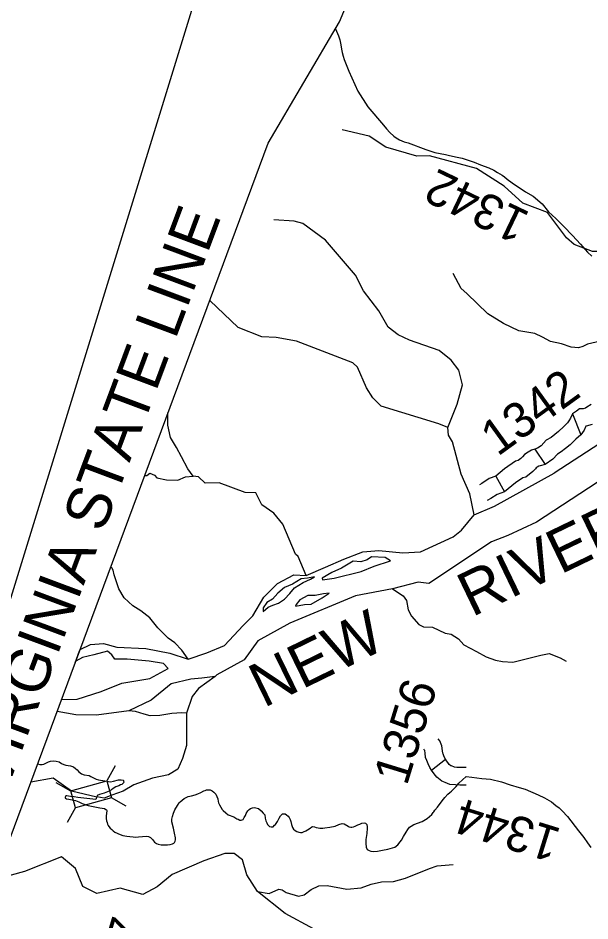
# Model space of a CAD drawing. Extents: x 1347947 to 1350662, y 1027710 to 1030532.
# Drawn here: x 1348130.6 to 1348203.5, y 1028931.2 to 1029046.3 of the extents above; entities that cross this region are included whole.
import ezdxf

# ---------------------------------------------------------------- set-up
doc = ezdxf.new("R2010")
doc.units = 0
for name, color, linetype in [('Default', 7, 'Continuous'), ('Prop Leader Line Light', 7, 'Continuous'), ('Prop WCC CELL', 7, 'Continuous'), ('Sheet Data Field CELL', 7, 'Continuous')]:
    doc.layers.add(name, color=color, linetype=linetype)

msp = doc.modelspace()

# ---------------------------------------------------------------- linework, layer by layer
at = {"layer": 'Default'}
for p, q in [((1348201.31, 1028995.87), (1348202.37, 1028993.22)), ((1348196.49, 1028991.39), (1348197.83, 1028989.42)), ((1348191.55, 1028987.92), (1348192.66, 1028985.91)), ((1348137.86, 1028964.14), (1348138.42, 1028965.64)), ((1348183.33, 1028950.42), (1348185.12, 1028951.83)), ((1348142.97, 1028950.98), (1348141.9, 1028949.08)), ((1348137.31, 1028947.76), (1348135.42, 1028948.83)), ((1348144.39, 1028945.86), (1348142.5, 1028946.93)), ((1348137.9, 1028945.66), (1348136.83, 1028943.76))]:
    msp.add_line(p, q, dxfattribs=at)
for points in [[(1348083.52, 1028822.71), (1348089.97, 1028837.63), (1348104.26, 1028873.21), (1348113.82, 1028899.5), (1348162.49, 1029030.38), (1348171.57, 1029045.86), (1348180.52, 1029067.26), (1348186.85, 1029082.58), (1348194.68, 1029101.03), (1348199.8, 1029113.4)], [(1348171.06, 1029044.99), (1348171.45, 1029044.09), (1348171.62, 1029043.57), (1348171.75, 1029042.94), (1348171.85, 1029042.39), (1348171.94, 1029041.96), (1348172.04, 1029041.47), (1348172.17, 1029041.05), (1348172.43, 1029040.42), (1348172.78, 1029039.59), (1348173.93, 1029037.02), (1348175.2, 1029035.01), (1348177.2, 1029032.7), (1348177.58, 1029032.24), (1348178.01, 1029031.77), (1348178.52, 1029031.29), (1348178.81, 1029031.08), (1348179.01, 1029030.95), (1348179.23, 1029030.83), (1348179.85, 1029030.58), (1348180.36, 1029030.43), (1348182.6, 1029029.58), (1348183.77, 1029029.2), (1348185.13, 1029028.94), (1348185.62, 1029028.8), (1348186.58, 1029028.61), (1348187.23, 1029028.49), (1348187.87, 1029028.27), (1348188.77, 1029027.97), (1348189.58, 1029027.62), (1348190.64, 1029027.23), (1348191.28, 1029026.95), (1348191.73, 1029026.67), (1348192.05, 1029026.48), (1348192.35, 1029026.33), (1348192.63, 1029026.09), (1348192.99, 1029025.8), (1348193.6, 1029025.32), (1348195.34, 1029024.17), (1348196.31, 1029023.63), (1348197.45, 1029022.65), (1348198.26, 1029021.62), (1348199.21, 1029020.77), (1348200.21, 1029019.77), (1348201.3, 1029018.63), (1348202.33, 1029017.5), (1348203.21, 1029016.5), (1348203.79, 1029015.99)], [(1348204.8, 1029016.57), (1348203.86, 1029016.56), (1348201.53, 1029017.46), (1348200.55, 1029018.32), (1348198.13, 1029021.54), (1348194.97, 1029022.73), (1348192.59, 1029024.93), (1348189.06, 1029027.18), (1348183.06, 1029028.77), (1348181.45, 1029028.74), (1348177.5, 1029029.87), (1348175.38, 1029031.29), (1348171.91, 1029032.08)], [(1348185.39, 1028994.14), (1348186.59, 1028997.12), (1348187.29, 1028999.59), (1348186.83, 1029001.45), (1348185.84, 1029002.73), (1348184.32, 1029003.94), (1348180.54, 1029005.27), (1348179.07, 1029005.95), (1348177.8, 1029006.91), (1348176.6, 1029009.03), (1348174.67, 1029011.57), (1348173.65, 1029013.54), (1348169.8, 1029018.04), (1348166.9, 1029020.16), (1348165.8, 1029020.46), (1348163.2, 1029020.6)], [(1348207.84, 1029006.59), (1348205.83, 1029005.34), (1348203.22, 1029004.76), (1348202.64, 1029004.45), (1348202.08, 1029004.3), (1348201.14, 1029004.36), (1348199.91, 1029004.8), (1348198.52, 1029005.08), (1348197.49, 1029005.64), (1348196.53, 1029006.1), (1348194.47, 1029006.44), (1348192.53, 1029007.38), (1348190.52, 1029008.63), (1348187.82, 1029011.23), (1348187.13, 1029011.86), (1348186.11, 1029013.79)], [(1348185.39, 1028994.14), (1348184.28, 1028994.61), (1348176.91, 1028996.85), (1348175.84, 1028997.91), (1348175.02, 1028999.21), (1348173.89, 1029001.82), (1348173.31, 1029002.36), (1348166.12, 1029005.14), (1348163.51, 1029005.62), (1348161.66, 1029005.68), (1348158.67, 1029006.89), (1348155.04, 1029010.35)], [(1348203.69, 1028997.05), (1348203.15, 1028996.72), (1348202.96, 1028996.62), (1348202.69, 1028996.53), (1348202.22, 1028996.53), (1348201.83, 1028996.23), (1348201.31, 1028995.87), (1348201.04, 1028995.33), (1348200.86, 1028994.97), (1348200.68, 1028994.72), (1348200.2, 1028994.26), (1348199.55, 1028993.63), (1348199.05, 1028993.24), (1348198.59, 1028992.88), (1348197.97, 1028992.51), (1348197.31, 1028991.8), (1348196.86, 1028991.49), (1348196.49, 1028991.39), (1348196.1, 1028991.23), (1348195.64, 1028990.99), (1348195.21, 1028990.68), (1348194.94, 1028990.4), (1348194.74, 1028990.18), (1348194.4, 1028989.91), (1348194.04, 1028989.84), (1348192.66, 1028988.85), (1348191.55, 1028987.92), (1348190.7, 1028987.65), (1348189.76, 1028987), (1348189.43, 1028986.84)], [(1348152.9, 1028987.91), (1348152.22, 1028988.86), (1348151.43, 1028990.4), (1348150.78, 1028991.57), (1348150.01, 1028992.86), (1348149.68, 1028994.44), (1348149.68, 1028996.01)], [(1348203.82, 1028994.53), (1348203.06, 1028994.29), (1348203.03, 1028994.29), (1348202.79, 1028993.79), (1348202.37, 1028993.22), (1348201.76, 1028992.64), (1348201.03, 1028991.92), (1348200.43, 1028991.47), (1348199.88, 1028991.03), (1348199.39, 1028990.74), (1348198.79, 1028990.09), (1348197.83, 1028989.42), (1348197.2, 1028989.25), (1348197.04, 1028989.19), (1348196.82, 1028989.07), (1348196.69, 1028988.98), (1348196.58, 1028988.86), (1348196.27, 1028988.52), (1348195.38, 1028987.82), (1348194.96, 1028987.73), (1348194.04, 1028987.07), (1348192.66, 1028985.91), (1348191.69, 1028985.6), (1348190.91, 1028985.07), (1348190.45, 1028984.83)], [(1348221.39, 1028995.36), (1348214.11, 1028992.74), (1348211.12, 1028992.92), (1348209.06, 1028993.68), (1348207.27, 1028993.48), (1348204.79, 1028992.09), (1348198.97, 1028988.31)], [(1348188.79, 1028983), (1348188.2, 1028985.68), (1348187.13, 1028988.17), (1348186.02, 1028992.3), (1348185.49, 1028993.17), (1348185.39, 1028994.14)], [(1348224.13, 1028992.17), (1348222.1, 1028990.98), (1348211.59, 1028988.12), (1348206.93, 1028987.7), (1348204.48, 1028987.13), (1348196.74, 1028982.06), (1348193.07, 1028980.37), (1348191, 1028979.57), (1348182.98, 1028974.25), (1348181.62, 1028974.41), (1348178.33, 1028973.56), (1348173.63, 1028972.68), (1348165.25, 1028969.18), (1348161.18, 1028966.93), (1348159.42, 1028964.51), (1348155.92, 1028962.61), (1348155.72, 1028962.4)], [(1348138.49, 1028965.83), (1348139.8, 1028966.46), (1348141.47, 1028966.6), (1348143.19, 1028966.12), (1348146.89, 1028965.94), (1348149.95, 1028965.37), (1348152.29, 1028964.61), (1348154.65, 1028965.38), (1348156.93, 1028966.34), (1348159.3, 1028968.9), (1348160.55, 1028970.11), (1348161.92, 1028972.49), (1348163.68, 1028974.22), (1348165.75, 1028975.33), (1348167.33, 1028975.24), (1348169.82, 1028976.31), (1348172.13, 1028977.35), (1348174.56, 1028978.27), (1348176.59, 1028978.46), (1348179.65, 1028978.15), (1348181.91, 1028978.27), (1348186.09, 1028980.21), (1348187.14, 1028981.06), (1348188.79, 1028983), (1348191.38, 1028984.12), (1348198.97, 1028988.31)], [(1348146.7, 1028988.01), (1348146.99, 1028988.02), (1348147.39, 1028988.31), (1348147.97, 1028988.04), (1348148.27, 1028987.73), (1348149.51, 1028987.47), (1348150.95, 1028987.41), (1348151.96, 1028987.83), (1348152.9, 1028987.91)], [(1348167.33, 1028975.24), (1348166.3, 1028977.7), (1348165.97, 1028977.99), (1348164.35, 1028981.79), (1348163.2, 1028983.21), (1348161.66, 1028984.27), (1348160.92, 1028985.81), (1348159.54, 1028985.86), (1348156.22, 1028987.09), (1348154.47, 1028987.04), (1348153.58, 1028987.86), (1348152.9, 1028987.91)], [(1348169.4, 1028974.71), (1348170.9, 1028974.9), (1348174.34, 1028975.79), (1348176.03, 1028976.46), (1348178.09, 1028977.15), (1348177.4, 1028977.57), (1348175.67, 1028977.65), (1348175.11, 1028977.24), (1348174.32, 1028976.99), (1348173.33, 1028977.08), (1348171.83, 1028976.21), (1348170.6, 1028975.65), (1348169.37, 1028974.92), (1348169.4, 1028974.71)], [(1348152.29, 1028964.61), (1348151.46, 1028965.72), (1348150.59, 1028966.69), (1348149.74, 1028967.28), (1348148.41, 1028968.6), (1348147.38, 1028969.87), (1348146.24, 1028970.74), (1348145.21, 1028971.41), (1348144.13, 1028972.4), (1348143.42, 1028973.57), (1348142.82, 1028975.35), (1348142.72, 1028975.94), (1348142.56, 1028976.25), (1348142.4, 1028976.37)], [(1348161.83, 1028970.69), (1348162.48, 1028971.22), (1348163.07, 1028971.48), (1348163.81, 1028971.72), (1348164.59, 1028972.23), (1348165.25, 1028972.95), (1348165.84, 1028973.69), (1348166.96, 1028974.35), (1348167.9, 1028974.81), (1348168.38, 1028975.07), (1348167.49, 1028974.94), (1348166.69, 1028974.83), (1348165.59, 1028974.17), (1348164.57, 1028973.71), (1348163.74, 1028972.99), (1348163.04, 1028972.25), (1348162.33, 1028971.81), (1348161.83, 1028971.15), (1348161.83, 1028970.69)], [(1348165.97, 1028971.33), (1348167.12, 1028971.55), (1348167.96, 1028971.61), (1348169.36, 1028972.43), (1348170.26, 1028973.02), (1348169.55, 1028972.91), (1348168.48, 1028972.69), (1348167.56, 1028972.71), (1348166.52, 1028972.14), (1348166.08, 1028971.58), (1348165.97, 1028971.33)], [(1348178.33, 1028973.56), (1348179.71, 1028972.67), (1348180.15, 1028972.07), (1348180.34, 1028970.88), (1348180.77, 1028970.06), (1348181.69, 1028969.02), (1348182.3, 1028968.71), (1348183.45, 1028968.67), (1348185.07, 1028967.9), (1348185.85, 1028967.79), (1348186.77, 1028967.2), (1348187.47, 1028966.41), (1348189.06, 1028965.58), (1348190.3, 1028964.88), (1348191.48, 1028964.47), (1348192.37, 1028964.28), (1348193.7, 1028964.23), (1348197.27, 1028965.12), (1348198.36, 1028965.31), (1348199.76, 1028964.76), (1348200.52, 1028964.32)], [(1348136.11, 1028959.45), (1348138.12, 1028959.49), (1348141.17, 1028960.46), (1348143.82, 1028961.52), (1348147.4, 1028962.14), (1348149.72, 1028963.39), (1348149.12, 1028964.02), (1348147.3, 1028964.35), (1348144.48, 1028964.59), (1348142.94, 1028964.58), (1348142.53, 1028965.15), (1348141.99, 1028965.61), (1348140.26, 1028965.15), (1348138.79, 1028964.82), (1348137.93, 1028964.35)], [(1348155.72, 1028962.4), (1348154.04, 1028962.19), (1348152.63, 1028962.05), (1348150.1, 1028961.44), (1348147.57, 1028959.38), (1348144.73, 1028958.02)], [(1348155.72, 1028962.4), (1348153.58, 1028960.85), (1348152.8, 1028959.83), (1348152.07, 1028957.72)], [(1348144.73, 1028958.02), (1348140.59, 1028957.47), (1348137.94, 1028957.48), (1348135.55, 1028957.93)], [(1348152.07, 1028957.72), (1348151.47, 1028957.75), (1348150.18, 1028957.66), (1348148.66, 1028957.42), (1348147.43, 1028957.38), (1348146.67, 1028957.59), (1348145.56, 1028957.91), (1348144.73, 1028958.02)], [(1348152.07, 1028957.72), (1348152.08, 1028953.57), (1348151.56, 1028951.91), (1348150.96, 1028950.57), (1348149.77, 1028949.86), (1348147.74, 1028949.43)], [(1348187.75, 1028950.76), (1348187.04, 1028950.76), (1348186.55, 1028950.79), (1348186.25, 1028950.82), (1348185.89, 1028950.98), (1348185.79, 1028951.01), (1348185.6, 1028951.17), (1348185.4, 1028951.4), (1348185.22, 1028951.64), (1348185.12, 1028951.83), (1348184.96, 1028952.15), (1348184.83, 1028952.51), (1348184.78, 1028952.62), (1348184.75, 1028952.9), (1348184.65, 1028953.56), (1348184.38, 1028954.18), (1348184.18, 1028954.45)], [(1348187.75, 1028948.51), (1348186.96, 1028948.51), (1348186.37, 1028948.55), (1348185.68, 1028948.61), (1348185.06, 1028948.88), (1348184.64, 1028949.03), (1348184.02, 1028949.56), (1348183.65, 1028949.99), (1348183.33, 1028950.42), (1348183.13, 1028950.79), (1348182.89, 1028951.25), (1348182.73, 1028951.68), (1348182.58, 1028952.05), (1348182.51, 1028952.61), (1348182.47, 1028952.93), (1348182.41, 1028953.05), (1348182.36, 1028953.12)], [(1348133.06, 1028951.25), (1348133.36, 1028951.18), (1348133.64, 1028951.16), (1348133.86, 1028951.22), (1348134.2, 1028951.38), (1348134.48, 1028951.5), (1348134.72, 1028951.59), (1348135.16, 1028951.61), (1348135.44, 1028951.57), (1348135.81, 1028951.48), (1348136.13, 1028951.29), (1348136.43, 1028951.17), (1348136.68, 1028951.09), (1348137.26, 1028950.99), (1348137.66, 1028950.86), (1348137.91, 1028950.64), (1348138.11, 1028950.46), (1348138.35, 1028950.22), (1348138.67, 1028949.95), (1348139.01, 1028949.84), (1348139.64, 1028949.76), (1348139.88, 1028949.63), (1348140.53, 1028949.3), (1348140.85, 1028949.2), (1348141.64, 1028949.06), (1348142.37, 1028948.93), (1348142.75, 1028949.02), (1348143.39, 1028949.19), (1348143.72, 1028949.2), (1348143.97, 1028949.17), (1348144.04, 1028949.12), (1348144.04, 1028949.04), (1348144.07, 1028948.97), (1348144.05, 1028948.83), (1348143.94, 1028948.72), (1348143.83, 1028948.63), (1348143.63, 1028948.55), (1348143.42, 1028948.45), (1348143.04, 1028948.31), (1348142.7, 1028948.08), (1348142.48, 1028947.92), (1348142.18, 1028947.75), (1348141.56, 1028947.5), (1348140.98, 1028947.35), (1348140.69, 1028947.2), (1348140.63, 1028947.02)], [(1348162.12, 1028944.32), (1348162.21, 1028943.97), (1348162.32, 1028943.71), (1348162.42, 1028943.52), (1348162.52, 1028943.38), (1348162.67, 1028943.24), (1348162.88, 1028943.2), (1348163.12, 1028943.21), (1348163.3, 1028943.41), (1348163.41, 1028943.49), (1348163.69, 1028943.87), (1348163.9, 1028944.31), (1348164.06, 1028944.6), (1348164.17, 1028944.73), (1348164.32, 1028944.85), (1348164.49, 1028944.88), (1348164.65, 1028944.87), (1348164.83, 1028944.74), (1348165.03, 1028944.59), (1348165.18, 1028944.41), (1348165.31, 1028944.14), (1348165.39, 1028943.9), (1348165.47, 1028943.52), (1348165.59, 1028943.13), (1348165.74, 1028942.93), (1348165.93, 1028942.75), (1348166.14, 1028942.6), (1348166.39, 1028942.53), (1348166.63, 1028942.49), (1348166.82, 1028942.48), (1348167.01, 1028942.56), (1348167.3, 1028942.68), (1348167.51, 1028942.83), (1348167.83, 1028943.05), (1348168.06, 1028943.19), (1348168.19, 1028943.25), (1348168.39, 1028943.2), (1348168.63, 1028943.13), (1348168.86, 1028943.08), (1348169.08, 1028943.03), (1348169.27, 1028943.03), (1348169.46, 1028943.04), (1348169.73, 1028943.1), (1348170.34, 1028943.18), (1348171.05, 1028943.29), (1348171.51, 1028943.5), (1348171.92, 1028943.62), (1348172.18, 1028943.61), (1348172.38, 1028943.47), (1348172.5, 1028943.41), (1348172.68, 1028943.28), (1348172.81, 1028943.23), (1348173.03, 1028943.15), (1348173.17, 1028943.17), (1348173.38, 1028943.22), (1348173.6, 1028943.29), (1348173.91, 1028943.45), (1348174.19, 1028943.56), (1348174.43, 1028943.68), (1348174.74, 1028943.74), (1348174.91, 1028943.66), (1348175.07, 1028943.52), (1348175.11, 1028943.23), (1348175.11, 1028943.06), (1348175.08, 1028942.38), (1348174.96, 1028941.59), (1348174.93, 1028941.07), (1348174.97, 1028940.61), (1348175.13, 1028940.31), (1348175.36, 1028940.21), (1348175.57, 1028940.12), (1348175.93, 1028940.07), (1348176.43, 1028940.12), (1348177.08, 1028940.24), (1348177.76, 1028940.37), (1348178.64, 1028940.62), (1348179.02, 1028940.92), (1348179.31, 1028941.3), (1348179.48, 1028941.52), (1348179.76, 1028941.97), (1348180.08, 1028942.52), (1348180.32, 1028942.88), (1348180.54, 1028943.15), (1348180.72, 1028943.31), (1348181.08, 1028943.52), (1348182.13, 1028943.89), (1348182.76, 1028944.29), (1348183.36, 1028944.79), (1348183.54, 1028945.03), (1348183.63, 1028945.14), (1348183.75, 1028945.34), (1348184.08, 1028945.74), (1348184.7, 1028946.53), (1348185.04, 1028946.95), (1348185.42, 1028947.36), (1348185.67, 1028947.58), (1348185.86, 1028947.76), (1348186.46, 1028948.34), (1348186.82, 1028948.77), (1348187.75, 1028949.63)], [(1348187.75, 1028949.63), (1348188.47, 1028949.55), (1348189.75, 1028949.37), (1348190.86, 1028949.27), (1348192.27, 1028948.95), (1348193.35, 1028948.58), (1348194.51, 1028948.21), (1348195.26, 1028948.02), (1348196.94, 1028947.28), (1348197.76, 1028946.91), (1348198.65, 1028946.38), (1348199.2, 1028945.94), (1348199.6, 1028945.63), (1348199.99, 1028945.23), (1348200.69, 1028944.51), (1348202.07, 1028942.7), (1348202.75, 1028941.86), (1348203.25, 1028941.18), (1348203.66, 1028940.58)], [(1348132.2, 1028948.93), (1348135.07, 1028949.48), (1348137.39, 1028947.81), (1348140.63, 1028947.02)], [(1348147.74, 1028949.43), (1348145.34, 1028948.55), (1348144, 1028947.77), (1348142.53, 1028947.27), (1348141.56, 1028946.88), (1348140.63, 1028947.02)], [(1348138.77, 1028946.19), (1348139.54, 1028945.94), (1348140.15, 1028945.82), (1348141, 1028945.65), (1348141.59, 1028945.53), (1348141.77, 1028945.44), (1348141.86, 1028945.39), (1348141.89, 1028945.31), (1348141.86, 1028944.92), (1348141.81, 1028944.6), (1348141.8, 1028944.29), (1348141.86, 1028943.98), (1348141.93, 1028943.76), (1348141.99, 1028943.55), (1348142.07, 1028943.4), (1348142.17, 1028943.25), (1348142.31, 1028943.05), (1348142.52, 1028942.86), (1348142.7, 1028942.7), (1348142.92, 1028942.53), (1348143.59, 1028942.25), (1348143.96, 1028942.12), (1348144.45, 1028942.01), (1348144.83, 1028941.96), (1348145.25, 1028941.92), (1348145.6, 1028941.91), (1348145.94, 1028941.94), (1348146.47, 1028941.96), (1348146.94, 1028942.02), (1348147.21, 1028941.97), (1348147.46, 1028941.86), (1348147.72, 1028941.59), (1348147.98, 1028941.25), (1348148.22, 1028941.08), (1348148.44, 1028940.98), (1348148.82, 1028940.93), (1348149.23, 1028940.91), (1348149.64, 1028940.91), (1348149.98, 1028940.96), (1348150.27, 1028941.05), (1348150.46, 1028941.13), (1348150.53, 1028941.21), (1348150.64, 1028941.37), (1348150.67, 1028941.54), (1348150.67, 1028941.8), (1348150.53, 1028942.41), (1348150.39, 1028943.05), (1348150.2, 1028943.85), (1348150.18, 1028944.19), (1348150.27, 1028944.52), (1348150.41, 1028944.95), (1348150.6, 1028945.36), (1348150.91, 1028945.94), (1348151.12, 1028946.26), (1348151.25, 1028946.42), (1348151.5, 1028946.62), (1348151.78, 1028946.82), (1348152.3, 1028947.06), (1348152.69, 1028947.15), (1348153.17, 1028947.29), (1348153.51, 1028947.41), (1348153.88, 1028947.58), (1348154.29, 1028947.82), (1348154.46, 1028947.86), (1348154.62, 1028947.91), (1348154.83, 1028947.95), (1348155.07, 1028947.91), (1348155.34, 1028947.8), (1348155.57, 1028947.62), (1348155.8, 1028947.38), (1348155.95, 1028947.07), (1348156.05, 1028946.78), (1348156.12, 1028946.46), (1348156.16, 1028946.27), (1348156.29, 1028946), (1348156.46, 1028945.72), (1348156.6, 1028945.42), (1348156.76, 1028945.29), (1348157.07, 1028944.99), (1348157.37, 1028944.76), (1348158.09, 1028944.47), (1348158.51, 1028944.25), (1348158.68, 1028944.18), (1348158.89, 1028944.08), (1348159.05, 1028944.04), (1348159.28, 1028944.13), (1348159.44, 1028944.39), (1348159.6, 1028944.67), (1348159.7, 1028944.9), (1348159.89, 1028945.24), (1348160.08, 1028945.44), (1348160.24, 1028945.55), (1348160.47, 1028945.63), (1348160.7, 1028945.66), (1348160.91, 1028945.65), (1348161.25, 1028945.54), (1348161.6, 1028945.24), (1348161.86, 1028944.97), (1348162.05, 1028944.73), (1348162.12, 1028944.32)], [(1348140.63, 1028947.02), (1348140.5, 1028946.69), (1348138.22, 1028946.96), (1348137.72, 1028947.04), (1348137.28, 1028947.09), (1348137.01, 1028947.13), (1348136.8, 1028947.16), (1348136.69, 1028947.15), (1348136.61, 1028947.08), (1348136.57, 1028946.99), (1348136.58, 1028946.92), (1348136.62, 1028946.88), (1348136.77, 1028946.77), (1348137.05, 1028946.73), (1348137.9, 1028946.56), (1348138.35, 1028946.42), (1348138.77, 1028946.19)], [(1348168.29, 1028930.21), (1348164.67, 1028932.15), (1348161.11, 1028934.98), (1348159.78, 1028937.07), (1348159.22, 1028939), (1348158.16, 1028939.82), (1348156.96, 1028939.79), (1348154.29, 1028938.89), (1348150.23, 1028937.14), (1348148.34, 1028935.57), (1348146.48, 1028934.59), (1348143.62, 1028935.4), (1348140.61, 1028934.72), (1348138.84, 1028935.59), (1348137.89, 1028937.88), (1348136.11, 1028939.39), (1348131.38, 1028937.53), (1348128.47, 1028936.69)], [(1348161.11, 1028934.98), (1348162.6, 1028934.69), (1348163.83, 1028935.28), (1348164.29, 1028935.16), (1348164.79, 1028934.84), (1348166.37, 1028934.39), (1348167.1, 1028934.55), (1348167.97, 1028935.2), (1348168.96, 1028935.67), (1348170.01, 1028935.71), (1348172.54, 1028935.25), (1348174.34, 1028935.44), (1348175.64, 1028935.9), (1348176.95, 1028936.19), (1348178.49, 1028936.23), (1348180.01, 1028936.65), (1348183.06, 1028937.91), (1348184.04, 1028938.22), (1348186.11, 1028938.41)]]:
    msp.add_lwpolyline(points, dxfattribs=at)
msp.add_lwpolyline([(1348142.5, 1028946.93), (1348137.9, 1028945.65), (1348137.3, 1028947.8), (1348141.9, 1028949.08)], close=True, dxfattribs=at)
at = {"layer": 'Prop WCC CELL'}
msp.add_line((1348175.36, 1029120.93), (1348067.18, 1028769.65), dxfattribs=at)

# ---------------------------------------------------------------- texts
at = {"layer": 'Default'}
for s, rotation, p in [('RIVER', 25.7241, (1348188.49, 1028969.92)), ('NEW', 26.0038, (1348161.92, 1028958.33))]:
    msp.add_text(s, height=5.625, rotation=rotation, dxfattribs=at).set_placement(p)
at = {"layer": 'Prop Leader Line Light'}
for s, rotation, p in [('1342', 154.4109, (1348196.08, 1029021.47)), ('1342', 35.9057, (1348191.76, 1028990.37)), ('1356', 72.8834, (1348180.17, 1028948.34)), ('1344', 162.73, (1348200.06, 1028942.91)), ('1317', 73.1949, (1348143.12, 1028917.93))]:
    msp.add_text(s, height=4.5, rotation=rotation, dxfattribs=at).set_placement(p)
at = {"layer": 'Sheet Data Field CELL'}
msp.add_text('VIRGINIA STATE LINE', height=5.625, rotation=69.5056, dxfattribs=at).set_placement((1348129.13, 1028947.7))
msp.add_text('VIRGINIA STATE LINE', height=5.625, rotation=69.5056, dxfattribs=at).set_placement((1348129.13, 1028947.7))

doc.saveas('drawing.dxf')
